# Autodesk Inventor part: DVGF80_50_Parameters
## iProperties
Created: 2010-04
Part Number: DVGF80_50_Parameters
Document SubType Name: Modeling
Designer: TB
Density: 1 g/cm^3
Slaglengde: 100.000 mm
Vinkel_Plussport: 0.00 deg
Vinkel_Minusport: 0.00 deg
Forlengelse_rør: 0.000 mm
Author: TB
